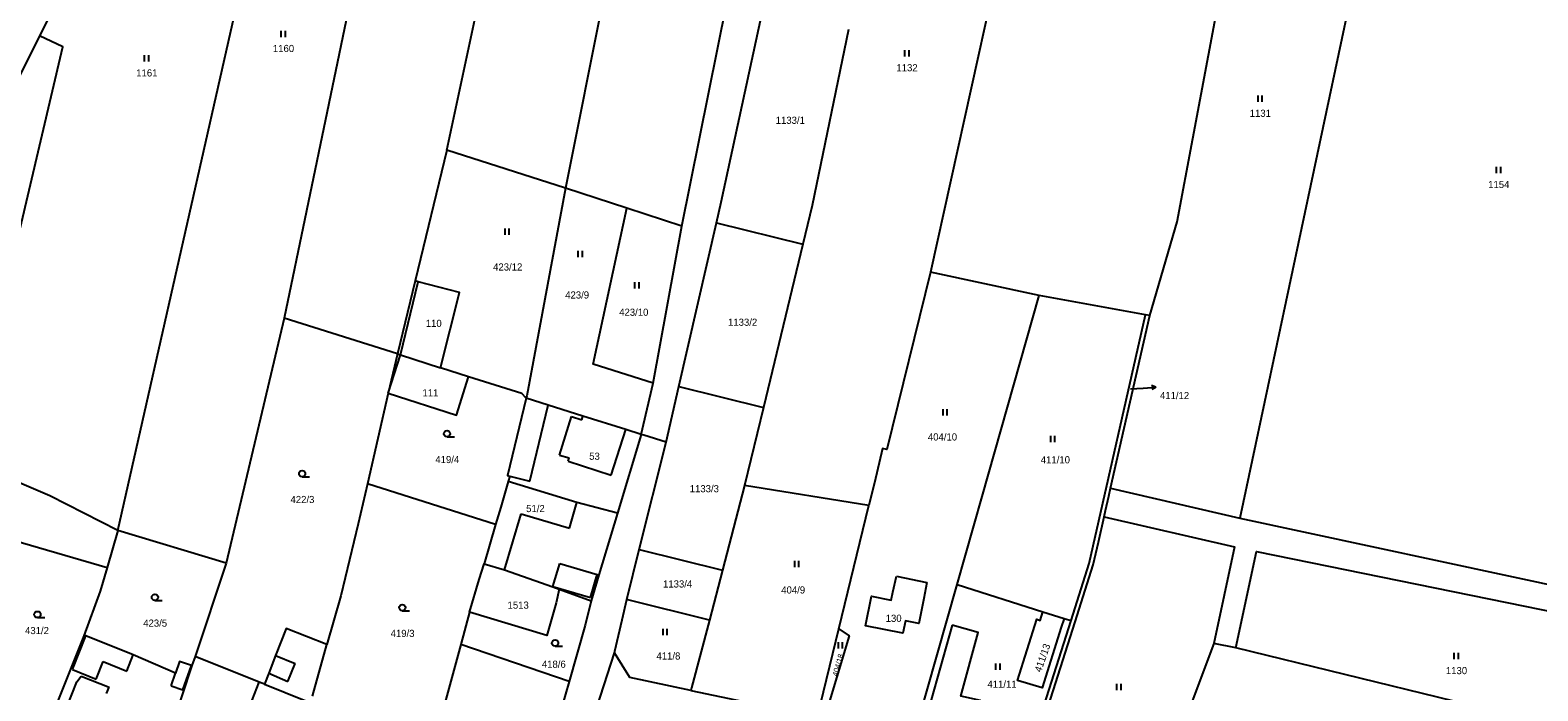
# Model space of a CAD drawing. Extents: x -746176 to -739709, y -1127410 to -1124482.
# Drawn here: x -742472.1 to -742113, y -1125910.5 to -1125753.1 of the extents above; entities that cross this region are included whole.
import ezdxf

# ---------------------------------------------------------------- set-up
doc = ezdxf.new("R2010")
doc.units = 0
for name, color, linetype in [('Hranice parcel', 7, 'Continuous'), ('Parcelní čísla', 7, 'Continuous'), ('Pop  PČ popisy', 7, 'Continuous'), ('Vnitřní kresba', 7, 'Continuous'), ('Značky kultur', 7, 'Continuous')]:
    doc.layers.add(name, color=color, linetype=linetype)

msp = doc.modelspace()

# ---------------------------------------------------------------- linework, layer by layer
at = {"layer": 'Hranice parcel'}
for p, q in [((-742372.93, -1125635.68), (-742411.59, -1125821.74)), ((-742372.85, -1125781.66), (-742342.86, -1125641.82)), ((-742315.89, -1125647.06), (-742344.65, -1125790.77)), ((-742225.54, -1125664.98), (-742257.65, -1125810.78)), ((-742144.45, -1125683.53), (-742183.95, -1125869.36)), ((-742372.85, -1125781.66), (-742380.43, -1125812.86)), ((-742344.65, -1125790.77), (-742372.85, -1125781.66)), ((-742344.65, -1125790.77), (-742353.81, -1125840.2)), ((-742329.98, -1125795.51), (-742344.65, -1125790.77)), ((-742316.92, -1125799.78), (-742329.98, -1125795.51)), ((-742323.73, -1125837.21), (-742316.92, -1125799.78)), ((-742317.61, -1125837.97), (-742308.64, -1125799.01)), ((-742308.64, -1125799.01), (-742288.1, -1125804.08)), ((-742288.1, -1125804.08), (-742297.47, -1125842.97)), ((-742231.78, -1125816.3), (-742257.65, -1125810.78)), ((-742380.43, -1125812.86), (-742384.66, -1125830.25)), ((-742411.59, -1125821.74), (-742425.41, -1125880.06)), ((-742384.66, -1125830.25), (-742411.59, -1125821.74)), ((-742214.78, -1125862.24), (-742205.45, -1125821.07)), ((-742205.45, -1125821.07), (-742206.44, -1125820.89)), ((-742384.66, -1125830.25), (-742386.83, -1125839.6)), ((-742367.68, -1125835.66), (-742374.35, -1125833.53)), ((-742386.83, -1125839.6), (-742391.8, -1125861.15)), ((-742353.81, -1125840.2), (-742353.96, -1125840.78)), ((-742326.59, -1125849.41), (-742323.73, -1125837.21)), ((-742320.67, -1125851.28), (-742317.61, -1125837.97)), ((-742317.61, -1125837.97), (-742297.47, -1125842.97)), ((-742297.47, -1125842.97), (-742301.95, -1125861.59)), ((-742326.59, -1125849.41), (-742332.22, -1125868.16)), ((-742327.06, -1125876.83), (-742320.67, -1125851.28)), ((-742361.26, -1125870.87), (-742391.8, -1125861.15)), ((-742301.95, -1125861.59), (-742307.2, -1125881.77)), ((-742272.35, -1125866.33), (-742301.95, -1125861.59)), ((-742214.78, -1125862.24), (-742183.95, -1125869.36)), ((-742279.49, -1125895.76), (-742272.35, -1125866.33)), ((-742491.48, -1125870.12), (-742453.8, -1125881.12)), ((-742451.26, -1125872.3), (-742453.8, -1125881.12)), ((-742425.41, -1125880.06), (-742451.26, -1125872.3)), ((-742361.26, -1125870.87), (-742364, -1125880.2)), ((-742183.95, -1125869.36), (-742094.09, -1125888.65)), ((-742330.04, -1125888.75), (-742327.06, -1125876.83)), ((-742327.06, -1125876.83), (-742307.2, -1125881.77)), ((-742425.41, -1125880.06), (-742432.86, -1125902.34)), ((-742307.2, -1125881.77), (-742310.3, -1125893.66)), ((-742265.76, -1125883.17), (-742258.57, -1125884.66)), ((-742346.08, -1125886.31), (-742338.49, -1125889.03)), ((-742261.6, -1125921.22), (-742251.35, -1125885.17)), ((-742251.35, -1125885.17), (-742230.88, -1125891.65)), ((-742367.46, -1125891.72), (-742369.56, -1125899.45)), ((-742230.88, -1125891.65), (-742225.86, -1125893.24)), ((-742225.86, -1125893.24), (-742224.19, -1125893.77)), ((-742459.32, -1125897.41), (-742466.99, -1125916.45)), ((-742284.56, -1125916.62), (-742279.49, -1125895.76)), ((-742404.91, -1125911.78), (-742401.44, -1125899.49)), ((-742369.56, -1125899.45), (-742376.04, -1125923.32)), ((-742343.77, -1125908.28), (-742369.56, -1125899.45)), ((-742190.21, -1125899.2), (-742212.05, -1125957.33)), ((-742184.93, -1125900.23), (-742190.21, -1125899.2)), ((-742433.58, -1125904.47), (-742443.02, -1125932.7)), ((-742432.86, -1125902.34), (-742433.58, -1125904.47)), ((-742337.98, -1125916.93), (-742332.93, -1125901.45)), ((-742314.74, -1125910.42), (-742295.02, -1125914.52))]:
    msp.add_line(p, q, dxfattribs=at)
for points in [[(-742404.87, -1125629.11), (-742430.87, -1125676.95), (-742469.87, -1125754.46)], [(-742451.26, -1125872.3), (-742423.93, -1125751.58), (-742396.6, -1125630.87)], [(-742316.92, -1125799.78), (-742306.23, -1125747.02), (-742297.45, -1125702.34), (-742289.42, -1125653.96)], [(-742205.45, -1125821.07), (-742198.92, -1125798.78), (-742183.97, -1125719.25), (-742174.2, -1125676.06)], [(-742308.64, -1125799.01), (-742307.5, -1125794.06), (-742297.49, -1125747.91)], [(-742277.21, -1125752.96), (-742285.89, -1125794.89), (-742288.1, -1125804.08)], [(-742469.87, -1125754.46), (-742479.12, -1125772.95), (-742512.08, -1125840.96), (-742525.31, -1125862.03), (-742533.06, -1125872.56), (-742535.93, -1125876.56)], [(-742487.36, -1125855.55), (-742487.11, -1125854.58), (-742474.85, -1125801.68), (-742464.37, -1125757.07), (-742469.87, -1125754.46)], [(-742323.73, -1125837.21), (-742337.99, -1125832.66), (-742329.98, -1125795.51)], [(-742257.65, -1125810.78), (-742268.09, -1125852.98), (-742269.07, -1125852.77), (-742269.89, -1125856.16), (-742270.81, -1125859.92), (-742272.35, -1125866.33)], [(-742374.35, -1125833.53), (-742369.89, -1125815.62), (-742379.68, -1125813.06), (-742380.43, -1125812.86)], [(-742251.35, -1125885.17), (-742245.39, -1125864.19), (-742231.78, -1125816.3)], [(-742206.44, -1125820.89), (-742230.01, -1125816.62), (-742231.78, -1125816.3)], [(-742224.19, -1125893.77), (-742219.86, -1125880.14), (-742206.44, -1125820.89)], [(-742384.66, -1125830.25), (-742383.94, -1125830.48), (-742374.35, -1125833.53)], [(-742386.83, -1125839.6), (-742370.58, -1125844.84), (-742367.68, -1125835.66)], [(-742353.96, -1125840.78), (-742354.98, -1125839.7), (-742367.68, -1125835.66)], [(-742353.96, -1125840.78), (-742358.42, -1125859.19), (-742357.84, -1125859.34), (-742358.23, -1125860.65)], [(-742326.59, -1125849.41), (-742330.25, -1125848.21), (-742340.45, -1125845.04), (-742348.72, -1125842.44), (-742353.96, -1125840.78)], [(-742320.67, -1125851.28), (-742325.99, -1125849.58), (-742326.59, -1125849.41)], [(-742451.26, -1125872.3), (-742467.46, -1125864.05), (-742487.36, -1125855.55)], [(-742391.8, -1125861.15), (-742394.01, -1125870.7), (-742398.15, -1125887.84), (-742401.44, -1125899.49)], [(-742358.23, -1125860.65), (-742360.05, -1125866.75), (-742361.26, -1125870.87)], [(-742332.22, -1125868.16), (-742341.91, -1125865.6), (-742358.23, -1125860.65)], [(-742216.33, -1125869.06), (-742215.99, -1125867.54), (-742215.21, -1125864.13), (-742214.78, -1125862.24)], [(-742332.22, -1125868.16), (-742336.64, -1125882.89), (-742338.49, -1125889.03)], [(-742241.51, -1125950.63), (-742233.66, -1125926.96), (-742223.23, -1125894.07), (-742218.91, -1125880.44), (-742217.69, -1125875.07), (-742216.33, -1125869.06)], [(-742216.33, -1125869.06), (-742185.29, -1125876.22), (-742190.21, -1125899.2)], [(-742184.93, -1125900.23), (-742180.03, -1125877.3), (-742095.09, -1125894.63)], [(-742453.8, -1125881.12), (-742455.42, -1125886.74), (-742459.32, -1125897.41)], [(-742367.46, -1125891.72), (-742365.16, -1125884), (-742364, -1125880.2)], [(-742364, -1125880.2), (-742359.13, -1125881.64), (-742347.65, -1125885.75), (-742346.08, -1125886.31)], [(-742258.57, -1125884.66), (-742259.27, -1125888.5), (-742260.46, -1125894.48), (-742263.65, -1125893.85), (-742264.23, -1125896.78), (-742273.15, -1125895.02), (-742271.72, -1125887.95), (-742267.02, -1125888.9), (-742266.64, -1125887), (-742265.76, -1125883.17)], [(-742346.08, -1125886.31), (-742346.82, -1125889.56), (-742349.06, -1125897.29), (-742367.46, -1125891.72)], [(-742338.49, -1125889.03), (-742339.9, -1125894.84), (-742343.77, -1125908.28)], [(-742332.93, -1125901.45), (-742332.83, -1125901.02), (-742331.14, -1125893.58), (-742330.04, -1125888.75)], [(-742310.3, -1125893.66), (-742329.73, -1125888.83), (-742330.04, -1125888.75)], [(-742310.3, -1125893.66), (-742314.57, -1125909.78), (-742314.74, -1125910.42)], [(-742239.87, -1125941.89), (-742234.61, -1125926.63), (-742224.19, -1125893.77)], [(-742225.86, -1125893.24), (-742226.52, -1125895.3), (-742231.11, -1125909.81), (-742236.97, -1125908.02), (-742232.36, -1125893.45), (-742231.54, -1125893.71), (-742230.88, -1125891.65)], [(-742433.58, -1125904.47), (-742433.71, -1125904.43), (-742436.54, -1125903.47), (-742437.49, -1125906.29), (-742447.62, -1125901.95), (-742458.86, -1125897.36), (-742459.32, -1125897.41)], [(-742401.44, -1125899.49), (-742411.12, -1125895.65), (-742413.66, -1125902.11), (-742415.31, -1125906.31), (-742416.34, -1125908.93), (-742417.54, -1125908.45), (-742432.86, -1125902.34)], [(-742279.49, -1125895.76), (-742277.04, -1125897.38), (-742282.91, -1125916.95)], [(-742252.47, -1125894.85), (-742259.69, -1125920.29), (-742243.08, -1125923.55), (-742241.58, -1125916.3), (-742246.33, -1125915.23), (-742245.79, -1125912.79), (-742250.41, -1125911.75), (-742246.32, -1125896.62), (-742252.47, -1125894.85)], [(-742139.76, -1125956.04), (-742133.02, -1125912.95), (-742184.93, -1125900.23)], [(-742314.74, -1125910.42), (-742329.26, -1125907.3), (-742332.93, -1125901.45)], [(-742343.77, -1125908.28), (-742352.46, -1125938.44), (-742353.05, -1125940.67)]]:
    msp.add_lwpolyline(points, dxfattribs=at)
at = {"layer": 'Pop  PČ popisy'}
for p, q in [((-742210.07, -1125838.56), (-742207, -1125838.36)), ((-742207, -1125838.36), (-742204.006, -1125838.151)), ((-742204.006, -1125838.151), (-742205.04, -1125837.721)), ((-742204.006, -1125838.151), (-742204.97, -1125838.72))]:
    msp.add_line(p, q, dxfattribs=at)
at = {"layer": 'Vnitřní kresba'}
for p, q in [((-742383.94, -1125830.48), (-742379.68, -1125813.06)), ((-742386.83, -1125839.6), (-742383.94, -1125830.48)), ((-742353.13, -1125860.51), (-742348.72, -1125842.44)), ((-742346.04, -1125854.34), (-742343.15, -1125845.16)), ((-742343.15, -1125845.16), (-742340.75, -1125845.96)), ((-742340.75, -1125845.96), (-742340.45, -1125845.04)), ((-742333.77, -1125859.09), (-742330.25, -1125848.21)), ((-742346.04, -1125854.34), (-742343.7, -1125855)), ((-742343.96, -1125855.81), (-742343.7, -1125855)), ((-742343.96, -1125855.81), (-742333.77, -1125859.09)), ((-742357.84, -1125859.34), (-742353.13, -1125860.51)), ((-742359.13, -1125881.64), (-742355.15, -1125868.33)), ((-742355.15, -1125868.33), (-742343.69, -1125871.72)), ((-742343.69, -1125871.72), (-742341.91, -1125865.6)), ((-742347.62, -1125885.65), (-742346, -1125880.14)), ((-742346, -1125880.14), (-742337.04, -1125882.77)), ((-742338.65, -1125888.24), (-742337.04, -1125882.77)), ((-742337.04, -1125882.77), (-742336.64, -1125882.89)), ((-742347.65, -1125885.75), (-742347.62, -1125885.65)), ((-742347.62, -1125885.65), (-742338.65, -1125888.24)), ((-742462.03, -1125905.4), (-742458.86, -1125897.36)), ((-742456.37, -1125907.69), (-742454.71, -1125903.47)), ((-742454.71, -1125903.47), (-742449.09, -1125905.82)), ((-742449.09, -1125905.82), (-742447.62, -1125901.95)), ((-742435.76, -1125910.23), (-742433.71, -1125904.43)), ((-742413.66, -1125902.11), (-742408.97, -1125903.96)), ((-742410.72, -1125908.26), (-742408.97, -1125903.96)), ((-742464.6, -1125917.38), (-742461.01, -1125908.34)), ((-742462.03, -1125905.4), (-742456.37, -1125907.69)), ((-742461.01, -1125908.34), (-742459.99, -1125907.02)), ((-742459.99, -1125907.02), (-742453.33, -1125909.63)), ((-742438.5, -1125909.28), (-742437.49, -1125906.29)), ((-742419.77, -1125914.17), (-742417.54, -1125908.45)), ((-742415.31, -1125906.31), (-742410.72, -1125908.26)), ((-742453.97, -1125911.14), (-742453.33, -1125909.63)), ((-742438.5, -1125909.28), (-742435.76, -1125910.23)), ((-742416.34, -1125908.93), (-742406.43, -1125912.88))]:
    msp.add_line(p, q, dxfattribs=at)
at = {"layer": 'Značky kultur'}
for p, q in [((-742412.311, -1125754.76), (-742412.311, -1125753.26)), ((-742411.31, -1125754.76), (-742411.31, -1125753.26)), ((-742444.861, -1125760.6), (-742444.861, -1125759.1)), ((-742443.86, -1125760.6), (-742443.86, -1125759.1)), ((-742263.791, -1125759.36), (-742263.791, -1125757.86)), ((-742262.79, -1125759.36), (-742262.79, -1125757.86)), ((-742179.641, -1125770.21), (-742179.641, -1125768.71)), ((-742178.64, -1125770.21), (-742178.64, -1125768.71)), ((-742122.841, -1125787.18), (-742122.841, -1125785.68)), ((-742121.84, -1125787.18), (-742121.84, -1125785.68)), ((-742359.021, -1125801.88), (-742359.021, -1125800.38)), ((-742358.02, -1125801.88), (-742358.02, -1125800.38)), ((-742341.571, -1125807.2), (-742341.571, -1125805.7)), ((-742340.57, -1125807.2), (-742340.57, -1125805.7)), ((-742328.061, -1125814.67), (-742328.061, -1125813.17)), ((-742327.06, -1125814.67), (-742327.06, -1125813.17)), ((-742254.671, -1125844.93), (-742254.671, -1125843.43)), ((-742253.67, -1125844.93), (-742253.67, -1125843.43)), ((-742372.833, -1125849.99), (-742371.083, -1125849.99)), ((-742229.031, -1125851.22), (-742229.031, -1125849.72)), ((-742228.03, -1125851.22), (-742228.03, -1125849.72)), ((-742407.333, -1125859.51), (-742405.583, -1125859.51)), ((-742290.021, -1125881.03), (-742290.021, -1125879.53)), ((-742289.02, -1125881.03), (-742289.02, -1125879.53)), ((-742442.413, -1125888.96), (-742440.663, -1125888.96)), ((-742470.383, -1125893.06), (-742468.633, -1125893.06)), ((-742383.483, -1125891.41), (-742381.733, -1125891.41)), ((-742321.381, -1125897.26), (-742321.381, -1125895.76)), ((-742320.38, -1125897.26), (-742320.38, -1125895.76)), ((-742347.083, -1125899.85), (-742345.333, -1125899.85)), ((-742279.621, -1125900.39), (-742279.621, -1125898.89)), ((-742278.62, -1125900.39), (-742278.62, -1125898.89)), ((-742242.071, -1125905.51), (-742242.071, -1125904.01)), ((-742241.07, -1125905.51), (-742241.07, -1125904.01)), ((-742132.911, -1125902.97), (-742132.911, -1125901.47)), ((-742131.91, -1125902.97), (-742131.91, -1125901.47)), ((-742213.261, -1125910.33), (-742213.261, -1125908.83)), ((-742212.26, -1125910.33), (-742212.26, -1125908.83))]:
    msp.add_line(p, q, dxfattribs=at)
for centre in [(-742372.833, -1125849.24), (-742407.333, -1125858.76), (-742442.413, -1125888.21), (-742383.483, -1125890.66), (-742470.383, -1125892.31), (-742347.083, -1125899.1)]:
    msp.add_circle(centre, 0.75, dxfattribs=at)

# ---------------------------------------------------------------- texts
at = {"layer": 'Parcelní čísla'}
for s, p in [('1160', (-742414.307, -1125758.32)), ('1132', (-742265.787, -1125762.91)), ('1161', (-742446.857, -1125764.15)), ('1131', (-742181.637, -1125773.76)), ('1133/1', (-742294.54, -1125775.43)), ('1154', (-742124.837, -1125790.73)), ('423/12', (-742361.85, -1125810.37)), ('423/9', (-742344.68, -1125817.04)), ('110', (-742377.89, -1125823.8)), ('423/10', (-742331.82, -1125821.15)), ('1133/2', (-742305.9, -1125823.53)), ('111', (-742378.68, -1125840.35)), ('411/12', (-742203.01, -1125840.993)), ('404/10', (-742258.29, -1125850.86)), ('419/4', (-742375.613, -1125856.24)), ('53', (-742338.962, -1125855.45)), ('411/10', (-742231.4, -1125856.3)), ('1133/3', (-742315.02, -1125863.19)), ('422/3', (-742410.113, -1125865.76)), ('51/2', (-742353.981, -1125867.92)), ('1133/4', (-742321.38, -1125885.88)), ('404/9', (-742293.22, -1125887.31)), ('1513', (-742358.407, -1125890.92)), ('423/5', (-742445.193, -1125895.21)), ('130', (-742268.344, -1125894.06)), ('431/2', (-742473.343, -1125896.98)), ('419/3', (-742386.263, -1125897.66)), ('411/8', (-742322.94, -1125903.04)), ('418/6', (-742350.24, -1125905)), ('1130', (-742134.907, -1125906.52)), ('411/11', (-742244.11, -1125909.76))]:
    msp.add_text(s, height=1.7, dxfattribs=at).set_placement(p)
for s, height, rotation, p in [('411/13', 1.7, 71, (-742231.342, -1125906.202)), ('404/18', 1.288, 74, (-742279.851, -1125907.145))]:
    msp.add_text(s, height=height, rotation=rotation, dxfattribs=at).set_placement(p)

doc.saveas('drawing.dxf')
